// Mitsubishi GX Works2 project: 运动控制指令   PLC: FX3U/FX3UC

PROGRAM MAIN
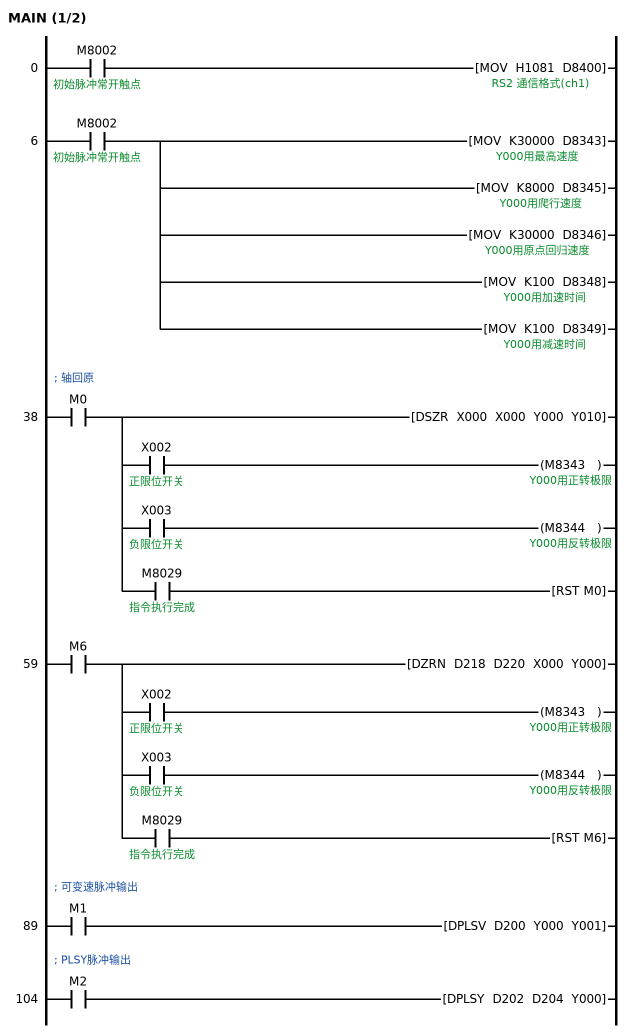
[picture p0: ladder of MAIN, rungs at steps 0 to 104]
0     LD      M8002  ; 初始脉冲常开触点
      MOV     H1081 D8400  ; RS2 通信格式(ch1)
6     LD      M8002  ; 初始脉冲常开触点
      MOV     K30000 D8343  ; Y000用最高速度
        [note] 最高速度
      MOV     K8000 D8345  ; Y000用爬行速度
        [note] 爬行速度
      MOV     K30000 D8346  ; Y000用原点回归速度
        [note] 原点回归速度
      MOV     K100 D8348  ; Y000用加速时间
        [note] 加速时间
      MOV     K100 D8349  ; Y000用减速时间
        [note] 减速时间
; 轴回原
38    LD      M0
      DSZR    X000 X000 Y000 Y010
      MPS
      AND     X002  ; 正限位开关
      OUT     M8343  ; Y000用正转极限
      MRD
      AND     X003  ; 负限位开关
      OUT     M8344  ; Y000用反转极限
      MPP
      AND     M8029  ; 指令执行完成
      RST     M0
59    LD      M6
      DZRN    D218 D220 X000 Y000
      MPS
      AND     X002  ; 正限位开关
      OUT     M8343  ; Y000用正转极限
      MRD
      AND     X003  ; 负限位开关
      OUT     M8344  ; Y000用反转极限
      MPP
      AND     M8029  ; 指令执行完成
      RST     M6
; 可变速脉冲输出
89    LD      M1
      DPLSV   D200 Y000 Y001
; PLSY脉冲输出
104   LD      M2
      DPLSY   D202 D204 Y000
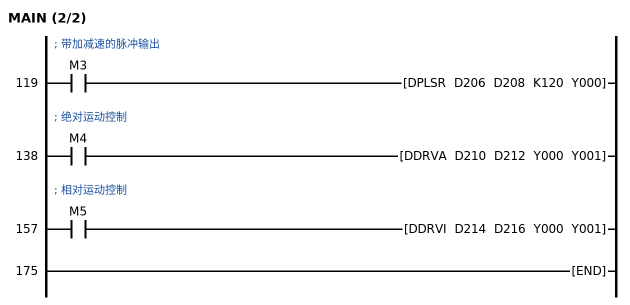
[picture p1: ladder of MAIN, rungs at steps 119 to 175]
; 带加减速的脉冲输出
119   LD      M3
      DPLSR   D206 D208 K120 Y000
; 绝对运动控制
138   LD      M4
      DDRVA   D210 D212 Y000 Y001
; 相对运动控制
157   LD      M5
      DDRVI   D214 D216 Y000 Y001
175   END
END_PROGRAM

// device comments not shown above
C10  ; CCD1拍照连续不良计数
C11  ; CCD2连续不良计数
